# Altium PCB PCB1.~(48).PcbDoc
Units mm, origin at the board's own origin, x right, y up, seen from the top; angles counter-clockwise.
Board outline 68 x 68 mm, 2 copper layers (Top Layer, Bottom Layer); 35 components, 24 nets, 106 pads, 17 vias.
Unrouted connection lines stored in the file: 2.
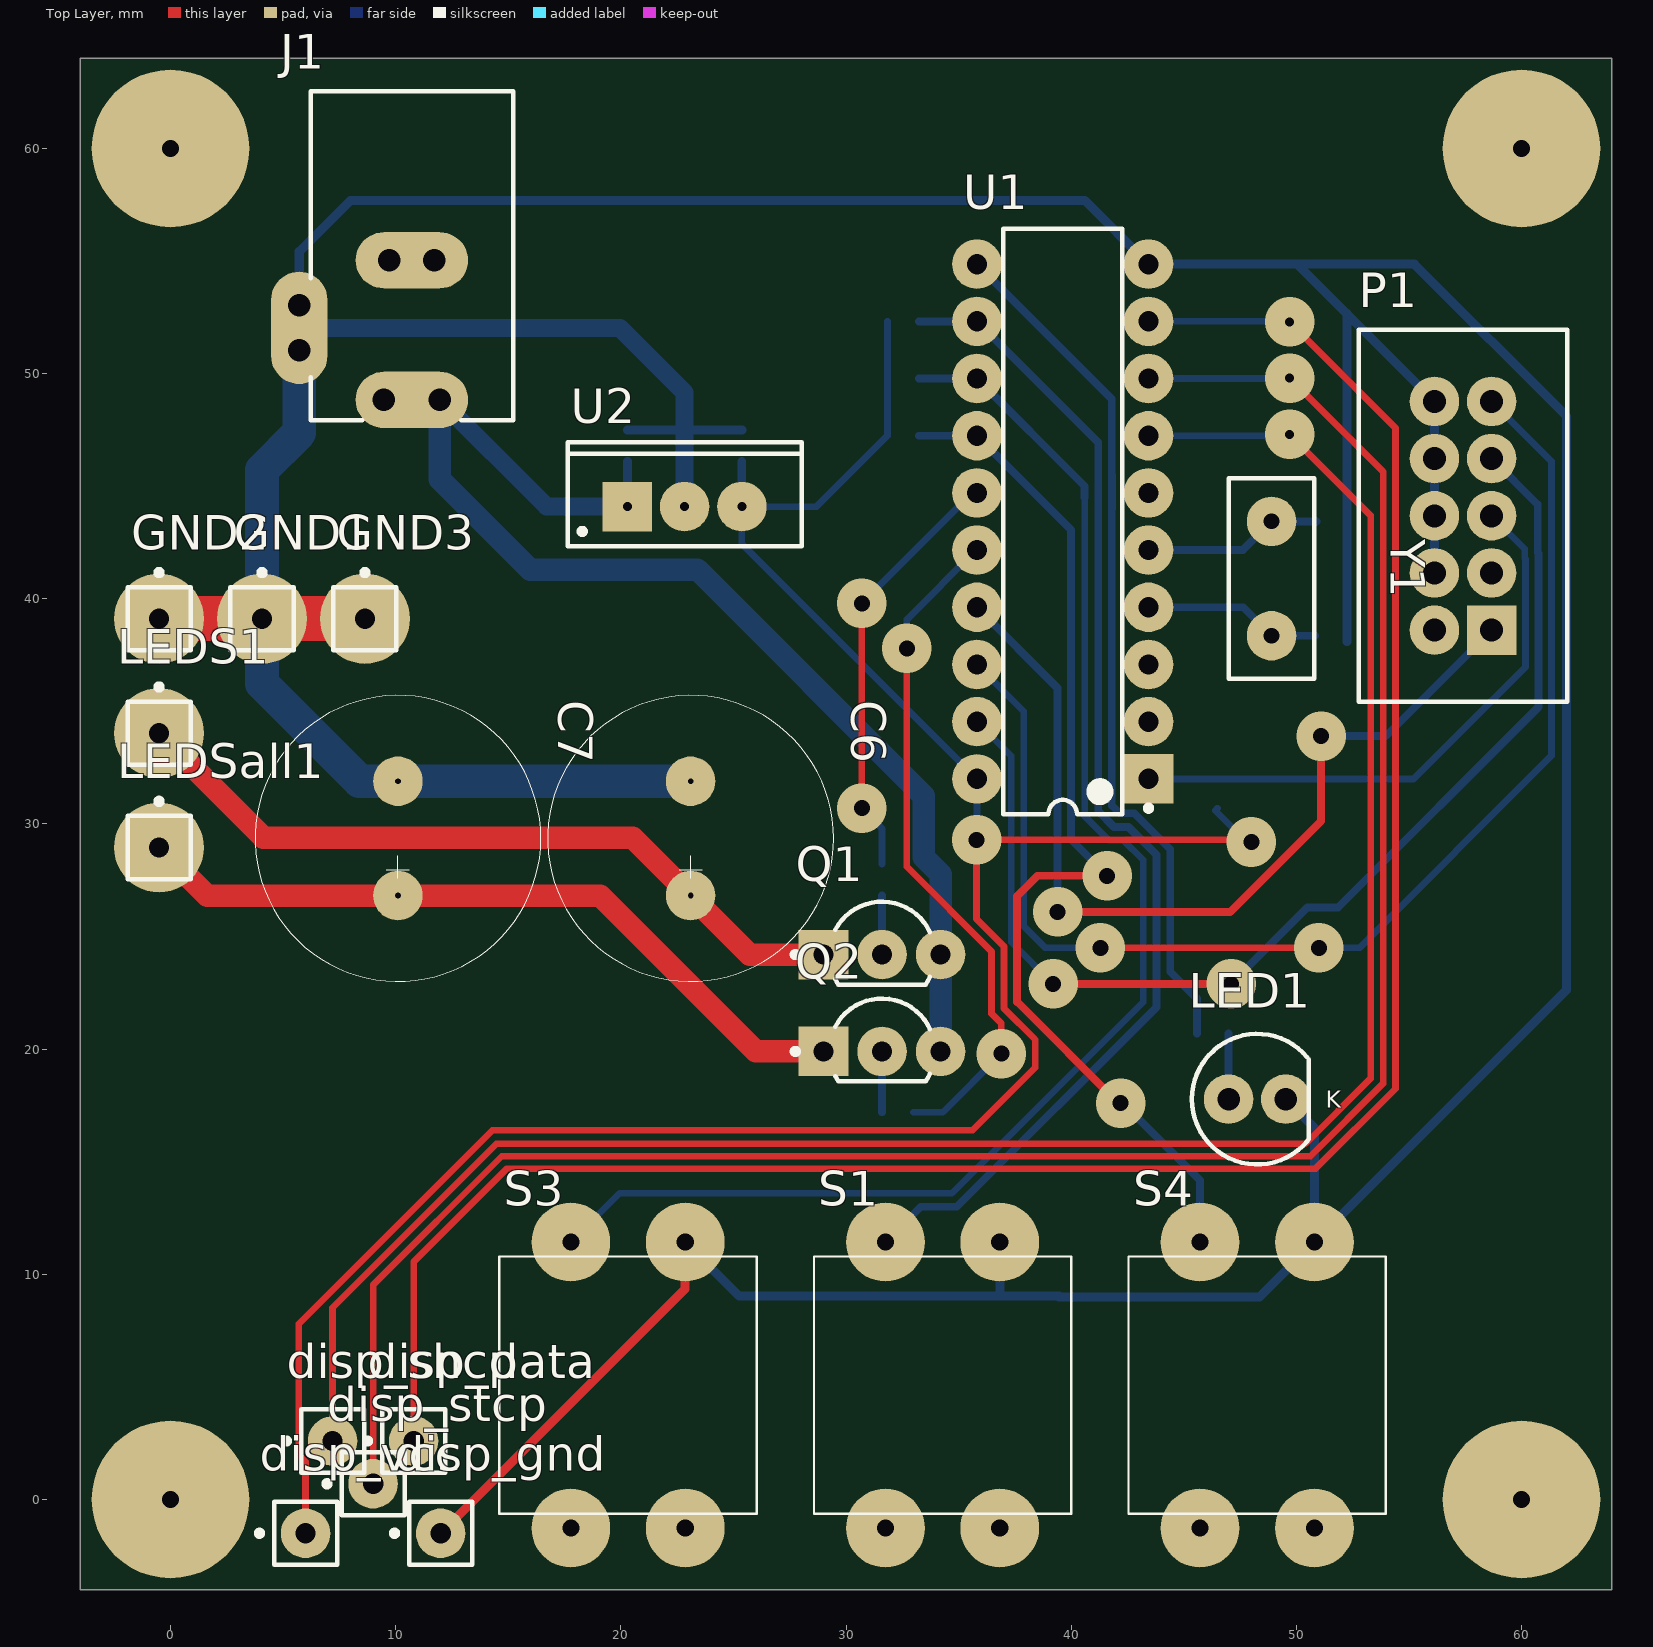
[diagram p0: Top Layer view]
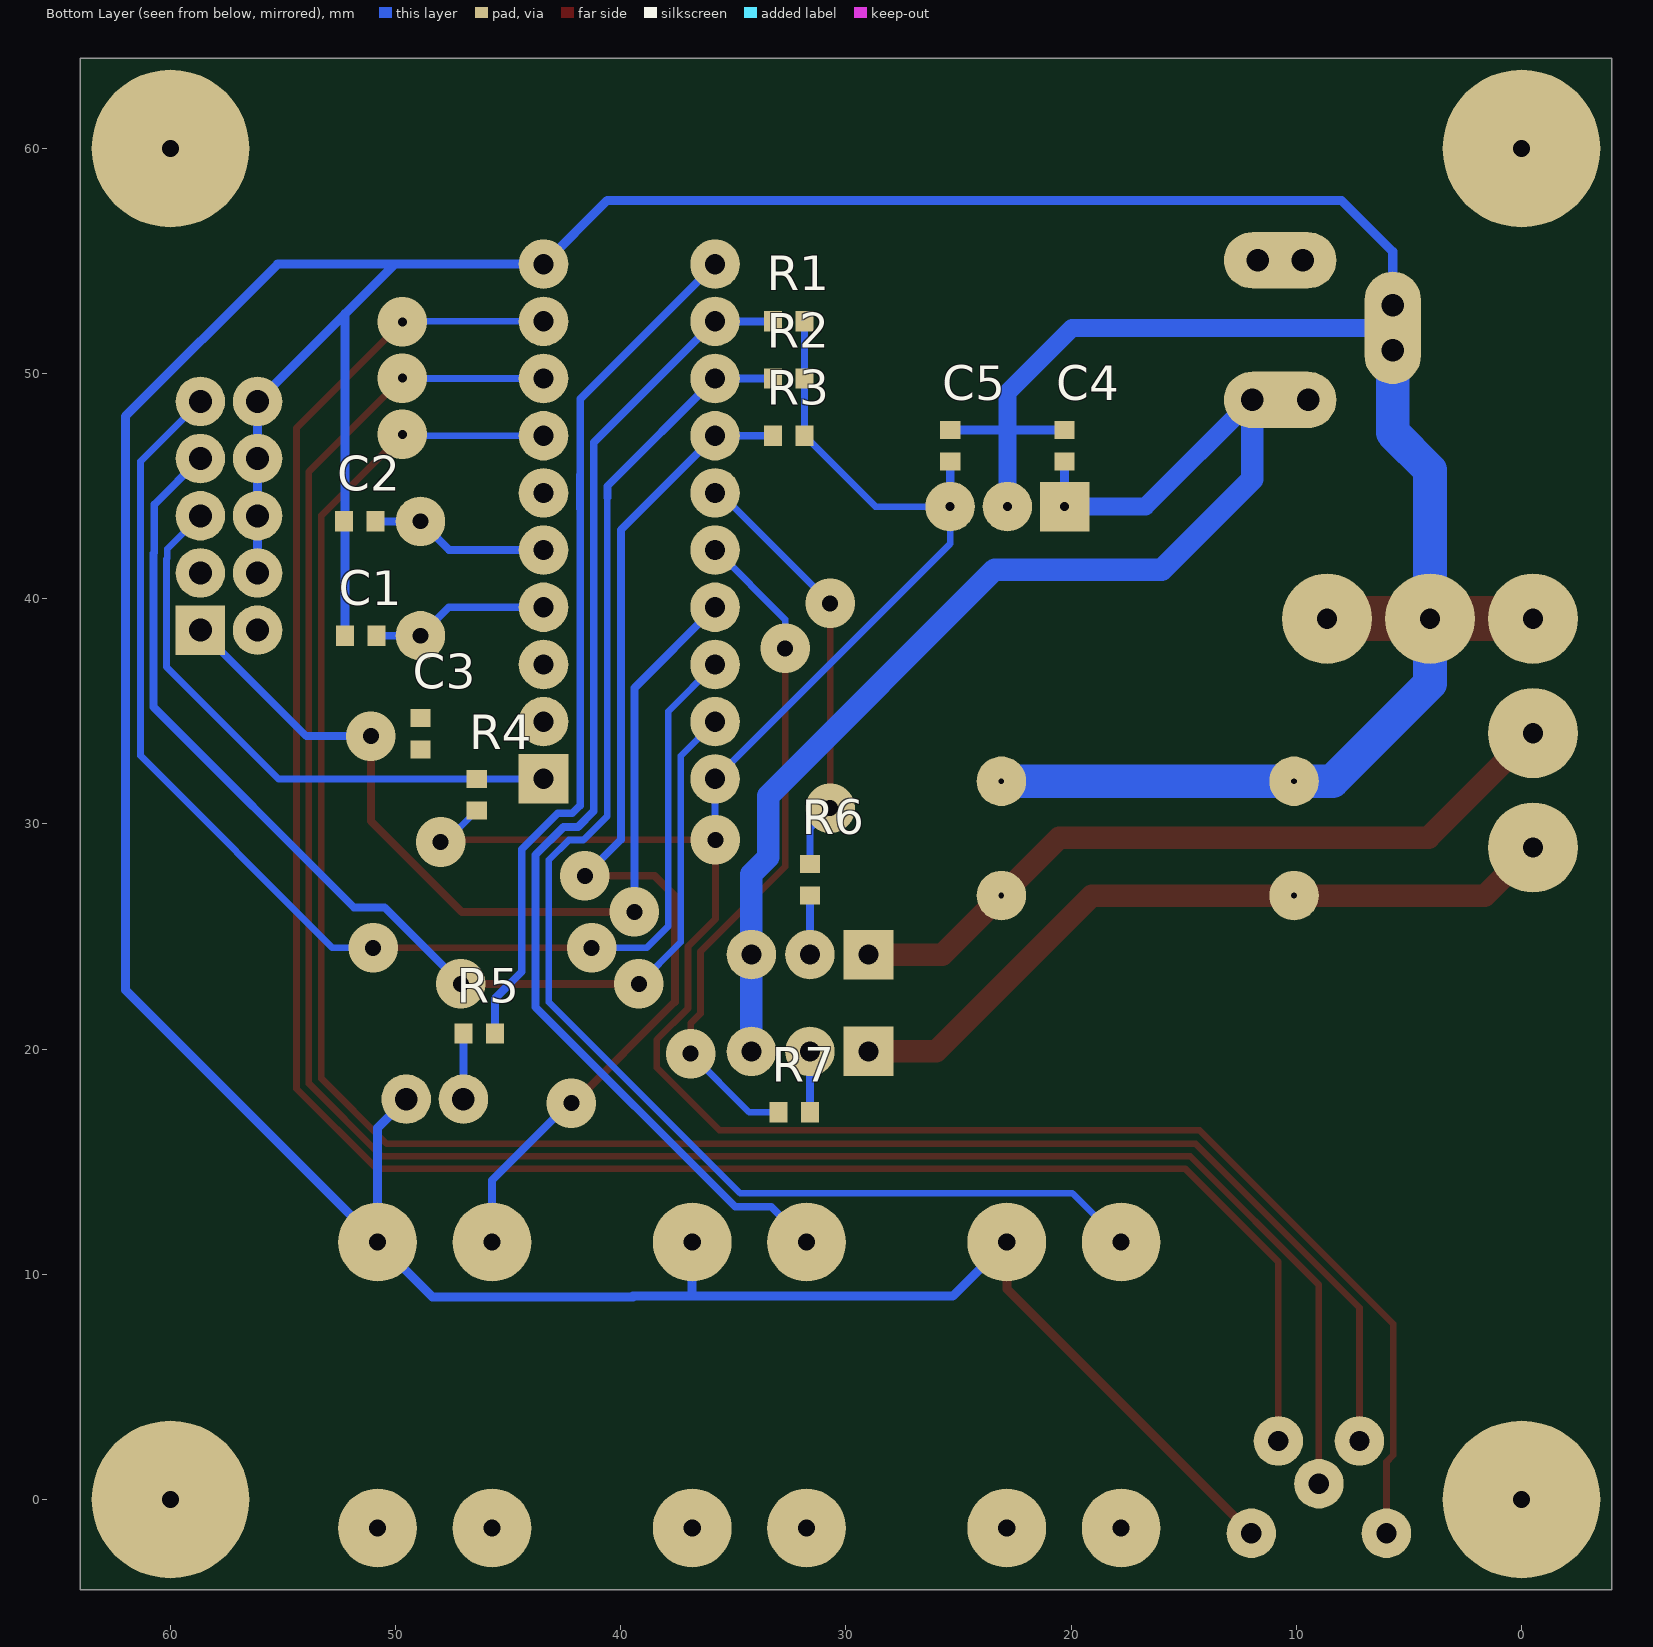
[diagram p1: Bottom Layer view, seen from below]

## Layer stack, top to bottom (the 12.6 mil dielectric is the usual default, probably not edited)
Top Solder: solder mask 0.0102, Solder Resist, Dk 3.5
Top Layer: signal copper 0.0356
Dielectric 1: dielectric 0.32, FR-4, Dk 4.8
Bottom Layer: signal copper 0.0356
Bottom Solder: solder mask 0.0102, Solder Resist, Dk 3.5

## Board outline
-4,-4 64,-4 64,64 -4,64

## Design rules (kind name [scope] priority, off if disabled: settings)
Clearance Clearance_U1_1 [InComponent('U1') vs IsRegion] p1: gap=0.254
Clearance Clearance_U1 [InComponent('U1') vs OnLayer('Top Layer')] p2: gap=0.178
Clearance [All] p3: gap=0.254
MinimumSolderMaskSliver [All] p1 off: minsoldermaskwidth=0.254
PasteMaskExpansion [All] p1 off: expansion=0
PolygonConnect [All] p1: connectstyle=Relief reliefconductorwidth=0.254 reliefentries=4 polygonreliefangle="90 Angle" airgapwidth=0.254
RoutingVias [All] p1: holewidth=0.711 width=1.27 viastyle="Through Hole" minholewidth=0.254 minwidth=0.508 maxholewidth=0.762 maxwidth=5
SolderMaskExpansion [All] p1 off: expansion=0.102
Width [All] p1: maxlimit=5 minlimit=0.3 preferedwidth=0.35
28 further rules are at their usual default settings.

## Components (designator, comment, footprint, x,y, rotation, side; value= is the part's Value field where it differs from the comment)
C1 "Cap Semi" CAPC1608L 51.54,38.36 r180 bottom
C2 "Cap Semi" CAPC1608L 51.6,43.44 r180 bottom
C3 "Cap Semi" CAPC1608L 48.9,34 r270 bottom
C4 "Cap Semi" CAPC1608L 20.3,46.8 r270 bottom
C5 "Cap Semi" CAPC1608L 25.375,46.8 r270 bottom
C6 "Cap1000uF30V" "Cap_1000uF_35V - duplicate" 23.1,31.9 r270 top
C7 "Cap1000uF30V" "Cap_1000uF_35V - duplicate" 10.1,31.9 r270 top
disp_data "uleds_all" PIN1#1 10.8,2.6 r90 top
disp_gnd "uleds_all" PIN1#1 12,-1.5 r90 top
disp_shcp "uleds_all" PIN1#1 7.2,2.6 r90 top
disp_stcp "uleds_all" PIN1#1 9,0.7 r90 top
disp_vcc "uleds_all" PIN1#1 6,-1.5 r90 top
GND1 "GNDout" PIN1#2 4.064,39.116 r0 top
GND2 "GNDout" PIN1#2 -0.508,39.116 r0 top
GND3 "GNDout" PIN1#2 8.636,39.116 r0 top
J1 "PWR2.5" PCBComponent_1 10.719,54.915 r270 top
LED1 "151051YS04000" "Type 5mm" 48.26,17.78 r0 top
LEDS1 "uleds" PIN1#2 -0.508,34.036 r0 top
LEDSall1 "uleds_all" PIN1#2 -0.508,28.956 r0 top
P1 "ZSS-105-01-F-D-450" SMTC-ZSS-105-01-X-D-450 58.674,38.608 r90 top
Q1 "2N5551" ONSC-TO-92-3-29-11_AM_BL 31.6,24.2 r0 top
Q2 "2N5551" ONSC-TO-92-3-29-11_AM_BL 31.6,19.9 r0 top
R1 "Res3" CAPC1608L 32.537,52.324 r0 bottom
R2 "Res3" CAPC1608L 32.537,49.784 r0 bottom
R3 "Res3" CAPC1608L 32.537,47.244 r0 bottom
R4 "Res3" CAPC1608L 46.4,31.304 r90 bottom
R5 "Res3" CAPC1608L 46.29,20.701 r0 bottom
R6 "Res3" CAPC1608L 31.6,27.52 r270 bottom
R7 "Res3" CAPC1608L 32.3,17.2 r180 bottom
S1 "START_min" key 34.29,5.08 r180 top
S3 "START_all" key 20.32,5.08 r180 top
S4 "PAUSE" key 48.26,5.08 r180 top
U1 "ATtiny2313V-10PU" 20P3 39.624,43.434 r180 top
U2 "MC78M05CTG" TO220 22.835,44.094 r0 top
Y1 "16MHz" "PCBComponent_1 - duplicate" 48.9,40.9 r0 top

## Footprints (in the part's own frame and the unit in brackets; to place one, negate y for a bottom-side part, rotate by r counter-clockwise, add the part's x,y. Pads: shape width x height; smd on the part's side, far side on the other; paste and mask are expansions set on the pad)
20P3 [mm] "DIP, 20-Pin, Row Spacing 7.62 mm, Pitch 2.54 mm"
  rect 2.2x2.2 hole 0.9: 1(-3.81,11.43)
  round 2.2 hole 0.9: 2(-3.81,8.89) 3(-3.81,6.35) 4(-3.81,3.81) 5(-3.81,1.27) 6(-3.81,-1.27) 7(-3.81,-3.81) 8(-3.81,-6.35) 9(-3.81,-8.89) 10(-3.81,-11.43) 11(3.81,-11.43) 12(3.81,-8.89) 13(3.81,-6.35) 14(3.81,-3.81) 15(3.81,-1.27) 16(3.81,1.27) 17(3.81,3.81) 18(3.81,6.35) 19(3.81,8.89) 20(3.81,11.43)
  silkscreen extent -3.94,-13 2.65,13, body extent -3.6,-12.95 3.6,12.95, height 5.08
"Cap_1000uF_35V - duplicate" [mm]
  round 2.2 hole 0.254: 1(5.08,0) 2(0,0)
  silkscreen extent -3.81,-6.35 8.89,6.35, body extent -3.81,-6.35 8.89,6.35, height 25.4
CAPC1608L [mm] "Chip Capacitor, Body 1.6x0.8mm, IPC High Density"
  rect 0.8x0.9 smd: 1(-0.7,0) 2(0.7,0)
  body extent -0.87,-0.48 0.87,0.48, height 1.3
key [mm]
  round 3.5 hole 0.762: 1(2.54,-6.35) 2(-2.54,-6.35) 3(-2.54,6.35) 4(2.54,6.35)
  silkscreen extent -5.72,-5.72 5.72,5.72, body extent -6.35,-6.35 6.35,6.35, height 11.94
ONSC-TO-92-3-29-11_AM_BL [mm] "TO, 3-Leads, Body Dia 4.7mm, Pitch 2.6mm"
  rect 2.2x2.2 hole 0.9: 1(-2.6,0)
  round 2.2 hole 0.9: 2(0,0) 3(2.6,0)
  silkscreen extent -3.97,-1.34 2.13,2.35, body extent -2.84,-1.34 2.84,2.35, height 5.33
PCBComponent_1 [mm]
  oval 2.5x5 all layers, no hole: 1(6.08,0) 2(-0.12,0)
  round 1.5 hole 1: 1A(6.08,-1.25) 1B(6.08,1.25) 2A(-0.12,-1) 2B(-0.12,1) 3A(1.88,-5) 3B(3.88,-5)
  oval 5x2.5 all layers, no hole: 3(2.88,-5)
  silkscreen extent -7.62,-4.5 6.98,4.5, body extent -7.87,-5.6 6.83,5.6, height 11
"PCBComponent_1 - duplicate" [mm]
  round 2.2 hole 0.7: 1(0,-2.54) 2(0,2.54)
  silkscreen extent -1.91,-4.44 1.91,4.44, body extent -2.33,-5.67 2.32,5.68, height 3.6
PIN1#1 [mm] "Connector; Plug"
  round 2.2 hole 0.9: 1(0,0)
  silkscreen extent -1.4,-1.4 1.4,2.17
PIN1#2 [mm] "Connector; Plug"
  round 4 hole 0.9: 1(0,0)
  silkscreen extent -1.4,-1.4 1.4,2.17
SMTC-ZSS-105-01-X-D-450 [mm] "Shrouded .025\" SQ Post Header, 2x5 Pins, Vertical, 2.54mm Pitch, Male"
  rect 2.2x2.2 hole 1.02: 1(0,0)
  round 2.2 hole 1.02: 2(0,2.54) 3(2.54,0) 4(2.54,2.54) 5(5.08,0) 6(5.08,2.54) 7(7.62,0) 8(7.62,2.54) 9(10.16,0) 10(10.16,2.54)
  silkscreen extent -3.18,-3.36 13.33,5.9, body extent -3.17,-3.57 13.34,5.91, height 11.43
TO220 [mm] "TO, Thru-Hole, Vertical, Heatsink Mounted; 3 In-Line Leads; Pitch 2.54 mm"
  rect 2.2x2.2 hole 0.4: 1(-2.54,0)
  round 2.2 hole 0.4: 2(0,0) 3(2.54,0)
  silkscreen extent -5.2,-1.75 5.2,2.85, body extent -5.25,-1.8 5.25,2.9, height 19.7
"Type 5mm" [mm] "THT, LED-5mm, 2pin- Body 5.8mm"
  round 2.2 hole 1: 1(1.27,0) 2(-1.27,0)
  silkscreen extent -2.9,-2.9 2.29,2.9, body extent -2.9,-2.9 2.5,2.9, height 11.7

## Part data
C1 C2 C3 C4 C5: "Capacitor (Semiconductor SIM Model)"
disp_data disp_gnd disp_shcp disp_stcp disp_vcc GND1 GND2 GND3 LEDS1 LEDSall1: library part Plug, "Plug"
J1: "Low Voltage Power Supply Connector"
LED1: library part CMP-1488-00010-1, "THT LED round mono-color color lens, WL-TMRW, Yellow"
P1: library part CMP-1024-00461-1
Q1 Q2: library part CMP-1048-01479-1, "Amplifier Transistor, NPN Silicon, 3-Pin TO-92, Pb-Free, Tape and Reel"
R1 R2 R3 R4 R5 R6 R7: "Resistor"
S1 S3 S4: library part SW-DPST, "Double-Pole, Single-Throw Switch"
U1: library part CMP-0093-00017-1, "Low Power tinyAVR® 8-Bit Microcontroller, 2K Flash Memory, 10MHz, Industrial Temperature, 20-Lead PDIP, Pb-Free"
U2: library part CMP-0244-00483-1, "Positive Voltage Regulator, 5V, 3-Pin TO-220"
Y1: library part XTAL, "Crystal Oscillator"

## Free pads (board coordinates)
  round 7 hole 0.762: 4(0,0) 5(60,0) 7(60,60) 8(0,60)

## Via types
v1: diameter 2.2, hole 0.711, Top Layer to Bottom Layer, 14 vias
v2: diameter 2.2, hole 0.4, Top Layer to Bottom Layer, 3 vias

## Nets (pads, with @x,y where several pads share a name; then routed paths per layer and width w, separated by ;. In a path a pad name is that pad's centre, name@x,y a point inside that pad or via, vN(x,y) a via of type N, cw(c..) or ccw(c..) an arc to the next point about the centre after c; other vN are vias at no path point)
+24V: C4.2 J1.1 J1.1A J1.1B Q1.3 Q2.3 U2.1 | length 54.9
  Bottom Layer w0.4: U2.1@20.3,44.1 C4.2
  Bottom Layer w0.8: J1.1B 16.709,44.094 U2.1
  Bottom Layer w1: J1.1B 11.969,45.3 15.969,41.3 23.4,41.3 33.446,31.254 33.446,28.532 34.2,27.778 Q2.3@34.2,19.8
BUT_PAUSE: R3.2 S4.1 U1.14 | length 47.7
  Top Layer w0.35: v1(41.6,27.7) 38.5,27.7 37.6,26.8 37.6,22.1 42.1,17.6 v1(42.2,17.6)
  Bottom Layer w0.35: R3.2 U1.14 40,43.058 40,29.3 v1(41.6,27.7) ; v1(42.2,17.6) 42.3,17.6 45.72,14.18 S4.1
BUT_START: R1.2 S1.1 U1.12 | length 53.1
  Bottom Layer w0.35: S1.1 33.32,13 34.919,13 43.796,21.877 43.796,28.623 42.548,29.871 41.906,29.871 41.2,30.577 41.2,44.246 41.204,44.25 41.204,45.248 41.2,45.252 41.2,46.938 U1.12 R1.2
BUT_STARTALL: R2.2 S3.1 U1.13 | length 63.5
  Bottom Layer w0.3: S3.1 19.95,13.6 34.7,13.6 43.2,22.1 43.2,28.4 42.308,29.292 41.666,29.292 40.6,30.358 40.6,44.5
  Bottom Layer w0.35: R2.2 U1.13 40.6,44.998 40.6,44.5
DISP_DATA: disp_data.1 U1.9 | length 97
  Top Layer w0.3: disp_data.1 10.8,10.55 14.942,14.692 50.859,14.692 54.408,18.241 54.408,47.592 v2(49.7,52.3)
  Bottom Layer w0.3: U1.9 49.676,52.324 v2(49.7,52.3)
DISP_SHCP: disp_shcp.1 U1.7 | length 92.6
  Top Layer w0.3: disp_shcp.1 7.2,8.517 14.483,15.8 50.4,15.8 53.3,18.7 53.3,43.7 v2(49.7,47.3)
  Bottom Layer w0.3: U1.7 49.644,47.244 v2(49.7,47.3)
DISP_STCP: disp_stcp.1 U1.8 | length 96.7
  Top Layer w0.3: disp_stcp.1 9,9.533 14.713,15.246 50.629,15.246 53.854,18.471 53.854,45.646 v2(49.7,49.8)
  Bottom Layer w0.3: U1.8 49.684,49.784 v2(49.7,49.8)
GND: C1.1 C2.1 C3.2 C4.1 C5.1 C6.2 C7.2 disp_gnd.1 GND1.1 GND2.1 GND3.1 J1.3 J1.3A J1.3B LED1.1 P1.4 P1.6 P1.8 P1.10 S1.2 S3.2 S4.2 U1.10 U2.2 | length 271.7
  Top Layer w0.4: disp_gnd.1 22.86,9.36 S3.2
  Top Layer w1.5: J1.3B J1.3
  Top Layer w2: GND2.1 GND1.1 GND3.1
  Bottom Layer w0.4: J1.3A 5.719,55.419 8,57.7 40.598,57.7 U1.10 50.038,54.864 ; C4.1 22.835,47.5 C5.1 ; S3.2 25.26,9.03 36.83,9.03 ; S1.2 36.83,9.03 ; 39.47,9 48.37,9 S4.2 ; 39.47,9.03 36.83,9.03 ; LED1.1 50.8,16.51 S4.2 ; C1.1@52.24,38.1 52.24,52.662 50.038,54.864 ; P1.4 P1.6 P1.8 P1.10 50.038,54.864 ; 50.038,54.864 55.236,54.864 62,48.1 62,22.63 S4.2
  Bottom Layer w0.8: J1.3A J1.3 19.965,52.035 22.835,49.165 U2.2
  Bottom Layer w1.5: J1.3B 5.719,47.375 4.064,45.72 GND1.1 4.064,36.236 8.4,31.9 C6.2@23.4,31.9
MISO: P1.9 U1.18 | length 56.7
  Top Layer w0.3: v1(41.3,24.5) 41.304,24.504 50.996,24.504 v1(51,24.5)
  Bottom Layer w0.3: U1.18 37.892,35.006 37.892,25.473 38.865,24.5 v1(41.3,24.5) ; v1(51,24.5) 52.8,24.5 61.336,33.036 61.336,46.106 P1.9
MOSI: P1.1 U1.17 | length 41.7
  Top Layer w0.35: v1(39.396,26.096) 47.058,26.096 51.1,30.138 v1(51.1,33.9)
  Bottom Layer w0.35: U1.17 39.396,36.042 v1(39.396,26.096) ; v1(51.1,33.9) 53.966,33.9 P1.1
NetC1_2: C1.2 U1.4 Y1.1 | length 7.9
  Bottom Layer w0.35: U1.4 47.636,39.624 Y1.1 C1.2
NetC2_2: C2.2 U1.5 Y1.2 | length 8
  Bottom Layer w0.35: U1.5 47.624,42.164 Y1.2 C2.2
NetC6_1: C6.1 LEDS1.1 Q1.1 | length 33.6
  Top Layer w1: LEDS1.1 4.128,29.4 20.52,29.4 C6.1 25.72,24.2 Q1.1
NetC7_1: C7.1 LEDSall1.1 Q2.1 | length 33.3
  Top Layer w1: LEDSall1.1 1.628,26.82 C7.1 19.08,26.82 26,19.9 Q2.1
NetJ1_2: J1.2 J1.2A J1.2B
NetLED1_2: LED1.2 R5.2 | length 2.9
  Bottom Layer w0.35: LED1.2 R5.2
NetQ1_2: Q1.2 R6.2 | length 2.6
  Bottom Layer w0.35: Q1.2 R6.2
NetQ2_2: Q2.2 R7.2 | length 2.7
  Bottom Layer w0.35: R7.2 Q2.2
NetR5_1: R5.1 U1.11 | length 38.6
  Bottom Layer w0.35: U1.11 41.804,48.874 41.804,45.502 41.808,45.498 41.808,44 41.804,43.996 41.804,30.827 42.156,30.475 42.798,30.475 44.4,28.873 44.4,23.438 45.59,22.248 R5.1
RES: C3.1 P1.5 R4.2 U1.1 | length 26.1
  Bottom Layer w0.3: U1.1 55.204,32.004 60.178,36.978 60.178,41.771 60.142,41.807 60.142,42.22 P1.5
SCK: P1.7 U1.19 | length 51.6
  Top Layer w0.35: v1(39.2,22.9) v1(47.1,22.9)
  Bottom Layer w0.3: U1.19 37.338,33.02 37.338,24.762 v1(39.2,22.9)
  Bottom Layer w0.35: v1(47.1,22.9) 50.5,26.3 51.858,26.3 60.757,35.199 60.757,40.115 60.757,40.285 60.757,42.011 60.721,42.047 60.721,44.181 P1.7
ULEDS: R6.1 U1.15 | length 22.2
  Top Layer w0.3: v1(30.7,30.7) v1(30.7,39.8) 30.7,40.598 30.8,40.698 31.304,40.194 v1@30.805,39.695
  Bottom Layer w0.3: v1(30.7,30.7) 31.6,29.8 R6.1 ; v1(30.7,39.8) 30.7,40.594 30.806,40.7 31.203,40.303 35.604,44.704 U1.15
ULEDSALL: R7.1 U1.16 | length 30.5
  Top Layer w0.3: v1(32.7,37.8) 32.7,28.1 36.467,24.333 36.467,21.576 36.9,21.144 v1(36.9,19.8)
  Bottom Layer w0.3: v1(32.7,37.8) 32.7,39.088 U1.16@35.776,42.164 ; R7.1 34.3,17.2 v1(36.9,19.8) v1@36.8,19.9
VCC: C5.2 disp_vcc.1 R1.1 R2.1 R3.1 R4.1 U1.20 U2.3 | length 107
  Top Layer w0.3: disp_vcc.1 6,1.673 5.696,1.977 5.696,7.796 14.3,16.4 35.627,16.4 38.404,19.177 38.404,20.423 37.021,21.806 37.021,24.562 35.8,25.783 v1(35.8,29.3) 47.9,29.3 v1(48,29.2)
  Bottom Layer w0.3: R1.1 R2.1 R3.1 28.688,44.094 U2.3 25.375,42.443 U1.20 35.814,29.586 35.528,29.3 v1(35.8,29.3) ; R4.1@46.498,30.702 R4.1 47.804,29.2 v1(48,29.2)
  Bottom Layer w0.381: U2.3 C5.2
pads on no net: P1.2 P1.3 S1.3 S1.4 S3.3 S3.4 S4.3 S4.4 U1.2 U1.3 U1.6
